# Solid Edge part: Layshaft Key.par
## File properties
Author: Nimesh.N
Template: iso metric part.par
Last saved by: Nimesh.N
Revision: 13
Application: Solid Edge
Username: Nimesh.N
Density: 7800.000 kg/m^3
Accuracy: 0.990
Material: Steel - Free Cutting:1.0764 , 36SMn14
Face Style: Steel
Fill Style: ANSI32(Steel)
Virtual Style: ANSI32(Steel)
Grouping: Steel\Steel - Free Cutting ( Higher P or S content)
LibraryName: Materials-DIN
Coef. of Thermal Exp: 1.1e-05
Thermal Conductivity: 14.0
Specific Heat: 440.0
Modulus of Elasticity: 210000003072.0
Poisson's Ratio: 0.28
Yield Stress: 420000000.0
Ultimate Stress: 670000000.0
Elongation: 0.0
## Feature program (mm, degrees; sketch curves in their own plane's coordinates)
sketch for "unnamed Protrusion 1" plane through (0, 0, 0) normal (0, -1, 0) x-axis (1, 0, 0)
  line (-10, 6) -> (10, 6)
  line (10, 6) -> (10, -6)
  line (10, -6) -> (-10, -6)
  line (-10, -6) -> (-10, 6)
  dimension (linear) = 10
  dimension (linear) = 10
extrude "unnamed Protrusion 1" add finite 40 along -normal
fillet "Round_1" radius 10
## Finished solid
Body 1: solid body, 6 faces, 12 edges, 8 vertices.
  Faces by surface: plane 4, cylinder 2
  Edges by curve: line 8, circle 4
Bounding box of the edges (mm): 20.000 x 40.000 x 12.000, from (-10, 0, -6) to (10, 40, 6).
Cylindrical faces by radius (mm): R10 x2
Planar faces by outward normal: +x 1, +z 1, -x 1, -z 1
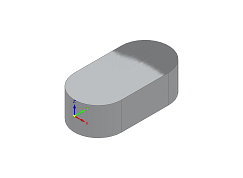
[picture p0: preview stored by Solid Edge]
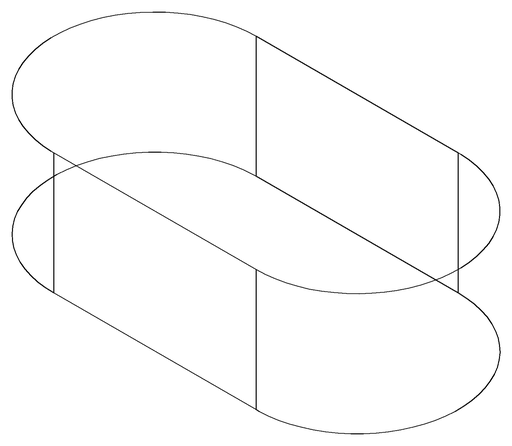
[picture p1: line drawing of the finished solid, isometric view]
